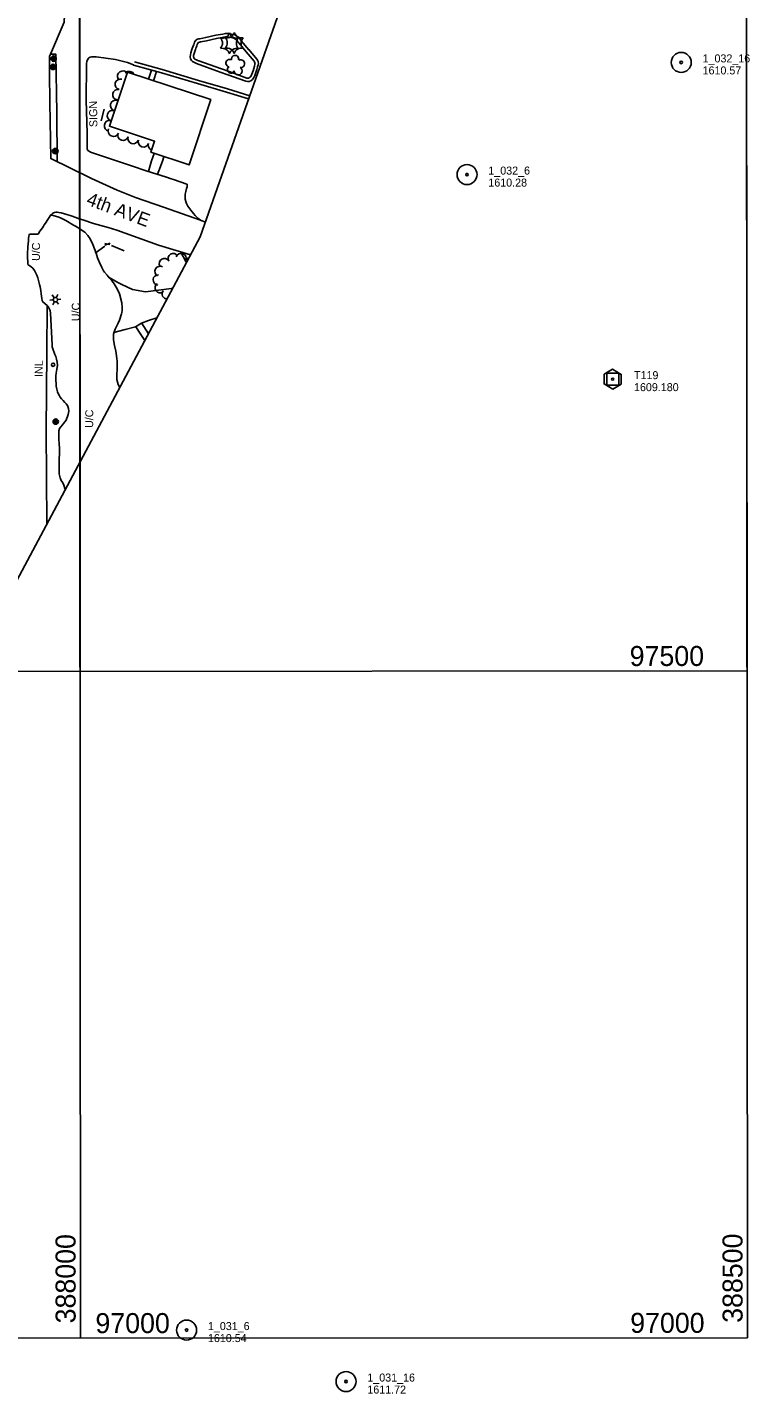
# Model space of a CAD drawing. Extents: x 189384 to 193282, y 256970 to 260388.
# Drawn here: x 191108 to 191650, y 256970 to 257995 of the extents above; entities that cross this region are included whole.
import ezdxf

# ---------------------------------------------------------------- set-up
doc = ezdxf.new("R2010")
doc.units = 0
for name, color, linetype in [('E_BMGRD', 7, 'Continuous'), ('E_DWY', 7, 'Continuous'), ('E_LAND_Vegetation', 7, 'Continuous'), ('E_MAP_Control', 7, 'Continuous'), ('E_MAP_GridLines', 7, 'Continuous'), ('E_MAP_Limits', 7, 'Continuous'), ('E_MAP_PassPoints', 7, 'Continuous'), ('E_MISCPROP', 7, 'Continuous'), ('E_MISCPROP_HvyLine', 7, 'Continuous'), ('E_MISCPROP_Railing', 7, 'Continuous'), ('E_PATH_Sidewalk', 7, 'Continuous'), ('E_RDWY', 7, 'Continuous'), ('E_RDWY_Name', 7, 'Continuous')]:
    doc.layers.add(name, color=color, linetype=linetype)

# ---------------------------------------------------------------- blocks, each defined once
blk = doc.blocks.new('TP')
at = {"layer": 'E_MAP_Control'}
for points in [[(-6.4, 3.8), (-6.4, -3.6), (0, -7.4), (6.4, -3.7), (6.4, 3.6), (-0.1, 7.4)], [(-4.5, -4.5), (-4.5, 4.5), (4.5, 4.5), (4.5, -4.5)]]:
    blk.add_lwpolyline(points, close=True, dxfattribs=at)
blk.add_circle((0, 0), 0.871, dxfattribs=at)
blk = doc.blocks.new('PP')
at = {"layer": 'E_MAP_PassPoints'}
for radius in [7.5, 0.96]:
    blk.add_circle((0, 0), radius, dxfattribs=at)
blk = doc.blocks.new('PP_1')
at = {"layer": 'E_MAP_PassPoints'}
for radius in [7.5, 0.96]:
    blk.add_circle((0, 0), radius, dxfattribs=at)
blk = doc.blocks.new('TREE_2')
at = {"layer": 'E_LAND_Vegetation'}
for centre, radius, start, end in [((-4.5, 0.2), 2.78, 78.0715, 279.0826), ((-1.5, 4.3), 2.78, 1.3945, 209.1675), ((3.6, 2.4), 2.97, 278.4236, 139.6575), ((-2, -4.2), 2.61, 140.7797, 358.7123), ((3.5, -3.4), 2.97, 196.0745, 79.0477)]:
    blk.add_arc(centre, radius, start, end, dxfattribs=at)
blk = doc.blocks.new('PINEL')
at = {"layer": 'E_LAND_Vegetation'}
for centre, start, end in [((-8.2, 7.3), 275.2112, 0.9761), ((-10.5, -3.4), 335.2112, 60.9761), ((2.2, 10.7), 215.2112, 300.9761), ((10.3, 3.3), 155.2112, 240.9761), ((-2.3, -10.8), 35.2112, 120.9761), ((8.1, -7.4), 95.2112, 180.9761)]:
    blk.add_arc(centre, 5.72, start, end, dxfattribs=at)
blk = doc.blocks.new('TP_1')
at = {"layer": 'E_MAP_Control'}
for points in [[(-6.4, 3.8), (-6.4, -3.6), (0, -7.4), (6.4, -3.7), (6.4, 3.6), (-0.1, 7.4)], [(-4.5, -4.5), (-4.5, 4.5), (4.5, 4.5), (4.5, -4.5)]]:
    blk.add_lwpolyline(points, close=True, dxfattribs=at)
blk.add_circle((0, 0), 0.871, dxfattribs=at)
blk = doc.blocks.new('PP_6')
at = {"layer": 'E_MAP_PassPoints'}
for radius in [7.5, 0.96]:
    blk.add_circle((0, 0), radius, dxfattribs=at)
blk = doc.blocks.new('PP_7')
at = {"layer": 'E_MAP_PassPoints'}
for radius in [7.5, 0.96]:
    blk.add_circle((0, 0), radius, dxfattribs=at)
blk = doc.blocks.new('UCR')
at = {"layer": 'E_RDWY_Name'}
blk.add_text('U/C', height=6, rotation=0.0001, dxfattribs=at).set_placement((-8.3, -2.6))
blk = doc.blocks.new('UCA')
at = {"layer": 'E_BMGRD'}
blk.add_text('U/C', height=6, rotation=359.9999, dxfattribs=at).set_placement((-8.3, -3))
blk = doc.blocks.new('INL_4')
at = {"layer": 'E_MISCPROP_Railing'}
blk.add_text('INL', height=6, rotation=360, dxfattribs=at).set_placement((-5.8, -2.7))
blk = doc.blocks.new('POLE_8')
at = {"layer": 'E_MISCPROP'}
for radius in [2.02, 1.52, 1.01, 0.502]:
    blk.add_circle((0, 0), radius, dxfattribs=at)
blk = doc.blocks.new('LTP_7')
at = {"layer": 'E_MISCPROP'}
for p, q in [((-1.6, 0.1), (-4.2, 0.1)), ((-0.8, 1.4), (-2, 3.7)), ((0.9, 1.4), (2.3, 3.7)), ((-0.9, -1.4), (-2.2, -3.6)), ((0.8, -1.5), (2, -3.6)), ((1.6, 0), (4.2, -0.1))]:
    blk.add_line(p, q, dxfattribs=at)
blk.add_circle((0, 0), 1.64, dxfattribs=at)
blk = doc.blocks.new('SIGN_7')
at = {"layer": 'E_MISCPROP'}
blk.add_text('SIGN', height=6, rotation=0.0001, dxfattribs=at).set_placement((-9.6, -3))

msp = doc.modelspace()

# ---------------------------------------------------------------- linework, layer by layer
at = {"layer": 'E_DWY'}
for points in [[(191252.8, 257961.2), (191235.1, 257967.6), (191233.9, 257968), (191233, 257968.5), (191232.1, 257969.1), (191231.3, 257969.8), (191230.6, 257971), (191230.2, 257972.5), (191230.4, 257974), (191230.7, 257975.6), (191231.3, 257977.4), (191231.8, 257978.9), (191232.2, 257980), (191232.6, 257980.9), (191232.9, 257981.7), (191233.2, 257982.6), (191233.5, 257983.5), (191234.4, 257985), (191235.8, 257985.8), (191236.7, 257986.1), (191237.5, 257986.2), (191242, 257987.2), (191249.4, 257988.8), (191254.7, 257989.7), (191256.7, 257990.1), (191258.9, 257990), (191261.2, 257989.6), (191262.9, 257989.3), (191264.9, 257988.5), (191266.2, 257987.4), (191267.4, 257986.2), (191268.2, 257985.1), (191268.6, 257984.7), (191274.2, 257977.9)], [(191253.7, 257963.5), (191236, 257969.9), (191235, 257970.3), (191234.2, 257970.7), (191233.6, 257971), (191233.2, 257971.4), (191232.9, 257972), (191232.7, 257972.7), (191232.8, 257973.5), (191233.2, 257975), (191233.7, 257976.6), (191234.2, 257978), (191234.5, 257979.1), (191234.9, 257980), (191235.2, 257980.8), (191235.6, 257981.8), (191235.8, 257982.4), (191236.2, 257983.2), (191236.8, 257983.5), (191237.4, 257983.7), (191238, 257983.8), (191242.6, 257984.7), (191249.9, 257986.4), (191255.2, 257987.3), (191256.9, 257987.6), (191258.6, 257987.5), (191260.8, 257987.1), (191262.2, 257986.9), (191263.6, 257986.3), (191264.6, 257985.5), (191265.5, 257984.5), (191266.3, 257983.5), (191266.7, 257983), (191272.3, 257976.3)], [(191274.2, 257978), (191280.2, 257970.9), (191280.7, 257970), (191281.3, 257969), (191281.4, 257967.7), (191281.2, 257966.6), (191280.8, 257965.1), (191280.3, 257963.2), (191279.8, 257961.5), (191279.3, 257960), (191278.7, 257958.5), (191278.1, 257957.2), (191277.6, 257956.3), (191276.9, 257955.5), (191275.8, 257954.6), (191274.4, 257954.2), (191273.2, 257954.1), (191272.1, 257954.3), (191258.5, 257959.1), (191252.8, 257961.2)], [(191130.4, 257930.5), (191129.5, 257974.6), (191125.5, 257974.7)], [(191187.9, 257966.5), (191183.4, 257968.3), (191174.3, 257970.5), (191167, 257971.7), (191159.7, 257972.6), (191156.2, 257972.5), (191155.3, 257972.4), (191154.4, 257971.9), (191153.7, 257971.3), (191152.8, 257969), (191152.6, 257967.7), (191152.5, 257966.8), (191152.5, 257966.6), (191152.4, 257940.2), (191153, 257915.4), (191153.1, 257903.5), (191153.2, 257902.9), (191153.6, 257902.3), (191154.1, 257902), (191154.8, 257901.6), (191155.3, 257901.3), (191155.6, 257901.2), (191187, 257890.6), (191197.4, 257887.2), (191212.6, 257882.3), (191216.1, 257881), (191217.7, 257880.6), (191227.7, 257877.2), (191228, 257877), (191227.9, 257875.2), (191227.5, 257873.9), (191227, 257871.6), (191226.6, 257869.6), (191226.5, 257867.6), (191226.6, 257865.9), (191226.9, 257864.1), (191227.5, 257862.6), (191228.6, 257860.7), (191230.8, 257857.5), (191231.8, 257856.3), (191232.8, 257855.1), (191234.1, 257853.7), (191236, 257851.7), (191238.7, 257849.7)], [(191188.6, 257968.8), (191209.4, 257963), (191236.5, 257954.9), (191258.2, 257948.5), (191274.9, 257943.4)], [(191272.3, 257976.3), (191278.2, 257969.4), (191278.6, 257968.8), (191278.8, 257968.2), (191278.9, 257967.8), (191278.8, 257967.1), (191278.4, 257965.7), (191277.9, 257963.9), (191277.5, 257962.2), (191277, 257960.9), (191276.4, 257959.5), (191275.9, 257958.4), (191275.5, 257957.7), (191275.1, 257957.3), (191274.6, 257956.9), (191274, 257956.7), (191273.3, 257956.6), (191272.7, 257956.7), (191259.4, 257961.5), (191253.7, 257963.5)], [(191187.9, 257966.4), (191208.7, 257960.6), (191235.8, 257952.5), (191257.5, 257946.1), (191274, 257941)], [(191130.6, 257893.9), (191130.4, 257930.5)], [(191125.7, 257854), (191121.7, 257847.8), (191120.9, 257846.6), (191120.2, 257845.5), (191119.5, 257844.4), (191118.5, 257843), (191117.6, 257841.8), (191116.9, 257840.7), (191116.5, 257839.9), (191115.9, 257839.6), (191114.8, 257839.7), (191113.6, 257839.7), (191112.1, 257839.7), (191110.9, 257839.7), (191109.9, 257839.6), (191109.6, 257839.2), (191109.3, 257838.2), (191109.1, 257836.4), (191109, 257834.6), (191108.8, 257832.4), (191108.6, 257830.2), (191108.5, 257828.3), (191108.4, 257826.3), (191108.4, 257824.5), (191108.4, 257822.6), (191108.4, 257821.2), (191108.5, 257819.9), (191108.5, 257818.5), (191108.5, 257817.6), (191108.6, 257816.9), (191109.2, 257816.4), (191110.1, 257815.9), (191111.1, 257815.2), (191112.4, 257814), (191113.5, 257812.3), (191114.5, 257810.4), (191115.3, 257808.8), (191116, 257806.8), (191116.7, 257804), (191117.3, 257801.8), (191117.7, 257800.1), (191118.2, 257797.3), (191118.6, 257795), (191118.9, 257793.1), (191119.1, 257791.5), (191119.4, 257790), (191119.7, 257788.8), (191123, 257786.1), (191123.9, 257785.2), (191124.4, 257784.5), (191124.9, 257783.4), (191125.2, 257782.2), (191125.5, 257780.5), (191126.7, 257756.6), (191126.9, 257755.2), (191127.5, 257753), (191128.2, 257750.8), (191128.8, 257749.3), (191129.5, 257747.8), (191130, 257745.9), (191130.5, 257743.7), (191130.7, 257741.5), (191130.6, 257739.7), (191130.3, 257738.3), (191129.8, 257735.4), (191129.6, 257733.4), (191129.5, 257731.7), (191129.5, 257729.8), (191129.7, 257727.7), (191129.9, 257725.7), (191130.3, 257723.3), (191130.9, 257721.4), (191131.6, 257719.7), (191132.2, 257718.5), (191132.8, 257717.5), (191133.8, 257716.1), (191135, 257714.9), (191136.4, 257713.4), (191137.4, 257712.3), (191138.3, 257711.1), (191139, 257708.8), (191139.2, 257706.8), (191138.9, 257704.4), (191137.2, 257700.2), (191136.4, 257698.9), (191135.4, 257697.6), (191134.5, 257696.6), (191133.2, 257695.1), (191132.4, 257693.9), (191131.9, 257692.1), (191131.7, 257689.1), (191131.9, 257685.9), (191132, 257682.4), (191132.2, 257679.2), (191132.2, 257676.7), (191132.3, 257674.4), (191132.1, 257671.7), (191132.1, 257669.4), (191132, 257666.6), (191132, 257663.4), (191132.1, 257661.5), (191132.1, 257660)], [(191125.7, 257854), (191131.7, 257852.4), (191133.5, 257851.5), (191137, 257849.8), (191142.8, 257846.4), (191144.3, 257845.7), (191146.8, 257844), (191149.4, 257842.4), (191151.4, 257841), (191153.6, 257838.7), (191155.2, 257836.2), (191157.3, 257831.9), (191159.8, 257825.3), (191160.9, 257821.8), (191162.4, 257818.3), (191164, 257814.6), (191165.3, 257812.2), (191166.1, 257811.2), (191168, 257808.8), (191169.6, 257806.9), (191171.2, 257805.2), (191173.4, 257802.4), (191175.6, 257798.6), (191177.3, 257794.9), (191179.1, 257788.1), (191179.3, 257784.7), (191179.2, 257782.4), (191179.1, 257780.9), (191178.9, 257780), (191177.2, 257775.2), (191176, 257772.4), (191174.1, 257768.5), (191172.9, 257764.6), (191172.9, 257760.5), (191173.6, 257756.2), (191174.5, 257751.8), (191175.1, 257748.5), (191175.4, 257746.1), (191175.6, 257744.6), (191175.6, 257741.9), (191175.5, 257738.4), (191175.3, 257734.5), (191175.4, 257730.6), (191176.3, 257726.8), (191177.5, 257724.6)], [(191227.4, 257818), (191227.1, 257819.1), (191223.3, 257826.2)], [(191169.5, 257807.1), (191176.1, 257803.5), (191179.1, 257801.9), (191187, 257798.1)], [(191187, 257798.1), (191196.9, 257796.4), (191216.2, 257798.9), (191217.5, 257799.5)], [(191205.4, 257776.9), (191199.1, 257774.8), (191193.7, 257773), (191189.4, 257770.1), (191181.5, 257768.1), (191173, 257766), (191173.3, 257766)], [(191132.1, 257660), (191132.2, 257658.8), (191132.7, 257657), (191133.6, 257654.8), (191134.7, 257653.1), (191135.6, 257651.3), (191136.4, 257648.8), (191136.5, 257647.7)]]:
    msp.add_lwpolyline(points, dxfattribs=at)
at = {"layer": 'E_LAND_Vegetation'}
for centre, radius, start, end in [((191179.8, 257958), 4.03, 38.8375, 207.4005), ((191184.6, 257957.7), 4.03, 26.5313, 138.9652), ((191176.2, 257944.2), 4.03, 78.9603, 258.945), ((191178, 257951.9), 4.03, 74.457, 254.4417), ((191174.5, 257936.1), 4.03, 74.242, 254.2267), ((191172.1, 257928.4), 4.03, 72.2782, 252.2629), ((191169.9, 257920.9), 4.03, 78.9154, 258.9001), ((191172.8, 257916.9), 4.03, 155.5716, 335.5563), ((191180, 257913.9), 4.03, 161.6565, 341.6411), ((191187.6, 257911.4), 4.03, 161.5905, 341.5752), ((191195.3, 257908.9), 4.03, 162.2434, 342.2281), ((191202.9, 257906.4), 4.03, 162.2434, 247.7683), ((191217.5, 257821.4), 3.85, 29.997, 209.9817), ((191223.5, 257821.4), 3.85, 341.6816, 161.6663), ((191207.7, 257811.7), 3.85, 60.084, 240.0687), ((191210.9, 257817.6), 3.85, 29.997, 209.9817), ((191229, 257817.7), 3.85, 85.1334, 134.6858), ((191206.3, 257805.3), 3.85, 86.5808, 266.5654), ((191207.7, 257799.5), 3.85, 125.0912, 305.0758), ((191213.1, 257794.8), 3.85, 141.5802, 268.1819)]:
    msp.add_arc(centre, radius, start, end, dxfattribs=at)
at = {"layer": 'E_MAP_GridLines'}
for p, q in [((191147.8, 257511.8), (191146.7, 259011.8)), ((191647.8, 257512.2), (191646.7, 259012.2)), ((191148.1, 257011.8), (191147, 258511.8)), ((191648.1, 257012.2), (191647, 258512.2)), ((189647.8, 257510.7), (191647.8, 257512.2)), ((190147.8, 257511.1), (191647.8, 257512.2)), ((189648.1, 257010.7), (191648.1, 257012.2))]:
    msp.add_line(p, q, dxfattribs=at)
at = {"layer": 'E_MAP_Limits'}
msp.add_lwpolyline([(191295.4, 258001.9), (191237.8, 257837.5), (190873.2, 257154.6)], dxfattribs=at)
at = {"layer": 'E_MISCPROP'}
msp.add_line((191163.6, 257924.7), (191165.8, 257933.4), dxfattribs=at)
at = {"layer": 'E_MISCPROP_HvyLine'}
msp.add_lwpolyline([(191183.2, 257961.2), (191245.7, 257940.5), (191229.5, 257891.5), (191200.8, 257901), (191203.6, 257909.3), (191169.7, 257920.5)], close=True, dxfattribs=at)
at = {"layer": 'E_MISCPROP_Railing'}
for p, q in [((191166.2, 257831.4), (191170.4, 257832.8)), ((191166.3, 257832.5), (191170, 257831.8))]:
    msp.add_line(p, q, dxfattribs=at)
for points in [[(191159.1, 257825.3), (191166.2, 257830.7)], [(191171.3, 257831), (191180.7, 257827.1)]]:
    msp.add_lwpolyline(points, dxfattribs=at)
msp.add_circle((191127.5, 257741.7), 1.28, dxfattribs=at)
at = {"layer": 'E_PATH_Sidewalk'}
for points in [[(191201.4, 257962.6), (191199.1, 257955.9)], [(191202.8, 257954.7), (191205, 257961.6)], [(191203.2, 257900.2), (191201.3, 257894.7), (191200.3, 257891), (191199, 257886.7)], [(191205.9, 257884.5), (191207.4, 257888.3), (191209.7, 257895.2), (191210.5, 257897.8)], [(191193.8, 257773.1), (191197.2, 257767.6), (191199.1, 257765)], [(191189.5, 257770.2), (191193.3, 257764.5), (191195.9, 257760.6), (191196.4, 257759.9)]]:
    msp.add_lwpolyline(points, dxfattribs=at)
at = {"layer": 'E_RDWY'}
for points in [[(191137.4, 258058.9), (191137.6, 258036.6), (191135.8, 257998.6), (191124.7, 257972.9)], [(191241.7, 257848.7), (191238, 257850), (191210.2, 257859.9), (191189.4, 257867.2), (191175.5, 257872.5), (191156.2, 257881.3), (191140.5, 257889), (191125.7, 257896.3), (191125.1, 257938.3), (191124.7, 257960.4), (191124.7, 257972.9)], [(191125.7, 257854), (191126.2, 257854.4), (191127.1, 257855.1), (191127.8, 257855.6), (191128.6, 257855.9), (191129.6, 257856), (191130.5, 257856), (191131.9, 257855.8), (191133.6, 257855.5), (191136, 257854.9), (191138.5, 257854.2), (191140.3, 257853.7), (191141.9, 257853.1), (191143.9, 257852.3), (191145.8, 257851.6), (191147.3, 257851.1), (191148.9, 257850.6), (191149.7, 257850.3), (191157.8, 257847.7), (191168.9, 257844.5), (191175.4, 257842.5), (191206.6, 257831.3), (191230.6, 257824)], [(191122.9, 257622.4), (191122.4, 257692.4), (191122.9, 257751.1), (191123, 257786.1)]]:
    msp.add_lwpolyline(points, dxfattribs=at)

# ---------------------------------------------------------------- block references
at = {"layer": 'E_BMGRD'}
for p, xscale, yscale, rotation in [((191144.5, 257782.7), 0.9999981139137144, 0.9999981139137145, 89.49908557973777), ((191154.6, 257702.6), 0.9999981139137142, 0.9999981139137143, 89.49908539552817)]:
    msp.add_blockref('UCA', p, dxfattribs=dict(at, xscale=xscale, yscale=yscale, rotation=rotation))
at = {"layer": 'E_LAND_Vegetation'}
for name, p, rotation in [('PINEL', (191259.8, 257982.8), -18.35509441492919), ('PINEL', (191263.4, 257983), -18.355094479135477), ('TREE_2', (191264, 257966.3), -18.3550944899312)]:
    msp.add_blockref(name, p, dxfattribs=dict(at, rotation=rotation))
at = {"layer": 'E_MAP_Control', "rotation": 0.0001467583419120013}
for name in ['TP', 'TP_1']:
    msp.add_blockref(name, (191547, 257730.9), dxfattribs=at)
at = {"layer": 'E_MAP_PassPoints'}
for name, p, rotation in [('PP_1', (191598.4, 257968.4), 0.000145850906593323), ('PP_1', (191598.4, 257968.4), 0.000145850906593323), ('PP', (191437.8, 257884.3), 0.0001487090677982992), ('PP', (191437.8, 257884.3), 0.0001487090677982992), ('PP_6', (191227.6, 257017.9), -0.00011437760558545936), ('PP_7', (191347.1, 256979.3), -0.00011650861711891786)]:
    msp.add_blockref(name, p, dxfattribs=dict(at, rotation=rotation))
at = {"layer": 'E_MISCPROP'}
for name, p, xscale, yscale, rotation in [('POLE_8', (191127.4, 257965), 1.0000015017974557, 1.0000015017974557, 66.23274040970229), ('POLE_8', (191127.9, 257971.2), 1.0000015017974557, 1.000001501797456, 66.23274039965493), ('SIGN_7', (191157.6, 257929.5), 1.0000015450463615, 1.0000015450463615, 90.82913961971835), ('POLE_8', (191129.2, 257901.9), 1.0000015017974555, 1.0000015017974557, 66.2327403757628), ('LTP_7', (191129.2, 257790.5), 1.0000015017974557, 1.0000015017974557, 66.23274037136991), ('POLE_8', (191129.5, 257699.1), 1.0000015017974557, 1.000001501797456, 66.23274036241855)]:
    msp.add_blockref(name, p, dxfattribs=dict(at, xscale=xscale, yscale=yscale, rotation=rotation))
at = {"layer": 'E_MISCPROP_Railing', "xscale": 0.9999981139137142, "yscale": 0.9999981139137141, "rotation": 89.49908606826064}
msp.add_blockref('INL_4', (191117, 257738.3), dxfattribs=at)
at = {"layer": 'E_RDWY_Name', "xscale": 0.9999981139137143, "yscale": 0.9999981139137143, "rotation": 89.49908610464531}
msp.add_blockref('UCR', (191115.1, 257827.8), dxfattribs=at)

# ---------------------------------------------------------------- texts
at = {"layer": 'E_MAP_Control'}
for s, p in [('T119', (191563, 257730.9)), ('T119', (191563, 257730.9)), ('1609.180', (191563, 257721.9)), ('1609.180', (191563, 257721.9))]:
    msp.add_text(s, height=6, rotation=0, dxfattribs=at).set_placement(p)
at = {"layer": 'E_MAP_GridLines'}
for s, rotation, p in [('  97500  ', 0.0407, (191548.6, 257515.8)), ('  388000  ', 90.0407, (191144.4, 257011.8)), ('  388500  ', 90.0407, (191644.4, 257012.2)), ('  97000  ', 0.0407, (191148.1, 257015.6)), ('  97000  ', 0.0407, (191549, 257015.8))]:
    msp.add_text(s, height=15, rotation=rotation, dxfattribs=at).set_placement(p)
at = {"layer": 'E_MAP_PassPoints'}
for s, p in [('1_032_16', (191614.4, 257968.4)), ('1_032_16', (191614.4, 257968.4)), ('1610.57', (191614.4, 257959.4)), ('1610.57', (191614.4, 257959.4)), ('1_032_6', (191453.8, 257884.3)), ('1_032_6', (191453.8, 257884.3)), ('1610.28', (191453.8, 257875.3)), ('1610.28', (191453.8, 257875.3)), ('1_031_6', (191243.6, 257017.9)), ('1610.54', (191243.6, 257008.9)), ('1_031_16', (191363.1, 256979.3)), ('1611.72', (191363.1, 256970.3))]:
    msp.add_text(s, height=6, rotation=0, dxfattribs=at).set_placement(p)
at = {"layer": 'E_RDWY_Name'}
msp.add_text('4th AVE', height=10, rotation=339.4452, dxfattribs=at).set_placement((191151.8, 257862))

doc.saveas('drawing.dxf')
